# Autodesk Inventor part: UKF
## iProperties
Author: Administrator
Shininess: 41.0
PropertySet Name: _Private Model Information
Length Units: 11269
Angle Units: 11283
Time Units: 11279
Mass Units: 11290
Length Display Precision: 3
Angle Display Precision: 2
Compacted: True
Created: 2001-07
Part Number: UKF
Document SubType Name: Modellazione
Designer: Administrator
Control State: 0
Master: False
Checked Out: False
PropertySet Name: Design Tracking Control
Density: 7.86
Volumn: 632.3272709061713
Area: 1038.1924522947418
PropertySet Name: Model Information
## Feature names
1. Estrusione1 [Extrusion]
2. Raccordo1 [Fillet]
3. Estrusione2 [Extrusion]
4. Estrusione3 [Extrusion]
5. Raccordo2 [Fillet]
6. Raccordo3 [Fillet]
7. Raccordo4 [Fillet]
8. Raccordo8 [Fillet]
9. Foro1 [Hole]
10. Estrusione4 [Extrusion]
11. Raccordo5 [Fillet]
12. Rivoluzione5 [Revolution]
13. Rivoluzione6 [Revolution]
14. Raccordo7 [Fillet]
15. Rivoluzione7 [Revolution]
16. Rivoluzione9 [Revolution]
17. Estrusione5 [Extrusion]
18. Serie circolare6 [Circular Pattern]
